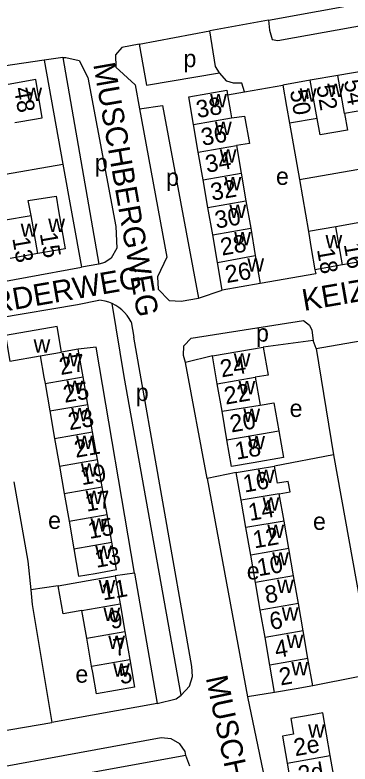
# Model space of a CAD drawing. Extents: x 162883 to 165538, y 383986 to 385172.
# Drawn here: x 164211.1 to 164288.3, y 384571.7 to 384744.4 of the extents above; entities that cross this region are included whole.
import ezdxf

# ---------------------------------------------------------------- set-up
doc = ezdxf.new("R2010")
doc.units = 0
for name, color, linetype in [('BLT_Basislijn', 7, 'Continuous'), ('BLT_Bebouwing', 7, 'Continuous'), ('BLT_Centroide', 7, 'Continuous'), ('BLT_Huisnummer', 7, 'Continuous'), ('BLT_Huisnummer_ tussenligend', 7, 'Continuous'), ('BLT_Onderverdeling_panden', 7, 'Continuous'), ('BLT_Straatnaam', 7, 'Continuous')]:
    doc.layers.add(name, color=color, linetype=linetype)

msp = doc.modelspace()

# ---------------------------------------------------------------- linework, layer by layer
at = {"layer": 'BLT_Basislijn'}
for p, q in [((164269.53, 384743.17), (164347.88, 384757.52)), ((164269.53, 384743.17), (164255.95, 384740.69)), ((164239.7, 384737.66), (164255.95, 384740.69)), ((164222.1, 384734.54), (164217.84, 384733.93)), ((164217.84, 384733.93), (164222.14, 384709.97)), ((164222.1, 384734.54), (164230.42, 384686.92)), ((164260.07, 384725.97), (164263.99, 384726.67)), ((164263.99, 384726.67), (164272.76, 384728.22)), ((164274.3, 384719.42), (164276.6, 384706.41)), ((164168.6, 384700.69), (164222.14, 384709.97)), ((164222.14, 384709.97), (164226.46, 384686.21)), ((164276.6, 384706.41), (164278.71, 384694.44)), ((164230.42, 384686.92), (164226.46, 384686.21)), ((164253.38, 384679.08), (164258.85, 384680.93)), ((164225.48, 384677.63), (164230.4, 384678.65)), ((164207.26, 384674.54), (164225.48, 384677.63)), ((164237.86, 384673.64), (164238.49, 384670.06)), ((164280.45, 384667.49), (164307.71, 384672.24)), ((164279.77, 384669.33), (164268.29, 384667.79)), ((164280.45, 384667.49), (164279.77, 384669.33)), ((164280.45, 384667.49), (164284.49, 384642.92)), ((164256.56, 384665.75), (164250.41, 384664.28)), ((164255.34, 384637.53), (164250.41, 384664.28)), ((164284.49, 384642.92), (164270.86, 384640.38)), ((164284.49, 384642.92), (164293.58, 384592.09)), ((164262.08, 384638.85), (164255.34, 384637.53)), ((164255.34, 384637.53), (164264.67, 384587.17)), ((164238.61, 384615.65), (164234.19, 384615.04)), ((164238.61, 384615.65), (164243.86, 384585.6)), ((164221.03, 384612.73), (164214.72, 384611.85)), ((164290.18, 384591.77), (164279.69, 384589.68)), ((164270.91, 384588.15), (164264.67, 384587.17)), ((164243.86, 384585.6), (164219.61, 384581.22)), ((164251.35, 384571.17), (164250.47, 384573.67))]:
    msp.add_line(p, q, dxfattribs=at)
for points in [[(164269.53, 384743.17), (164269.71, 384740.85), (164270.34, 384738.74), (164271.65, 384738.47), (164348.49, 384752.42), (164347.88, 384757.52)], [(164258.17, 384731), (164257.32, 384732.52), (164255.95, 384740.69)], [(164239.7, 384737.66), (164235.73, 384736.91), (164234.23, 384735.22), (164234.36, 384732.34), (164238.75, 384728.3), (164239.75, 384722.77)], [(164239.7, 384737.66), (164241.36, 384728.2), (164258.17, 384731)], [(164217.84, 384733.93), (164208.48, 384732.56), (164171.26, 384725.9), (164163.09, 384724.16), (164161.59, 384723.02), (164160.96, 384722.06), (164160.7, 384719.23), (164161.02, 384716.34), (164167.7, 384681.66), (164168.5, 384679.45), (164169.93, 384677.77), (164172.47, 384676.74), (164176.29, 384676.98), (164226.46, 384686.21)], [(164222.1, 384734.54), (164222.84, 384734.6), (164225.86, 384733.87), (164227.92, 384729.96), (164234.34, 384695.57), (164234.58, 384690.61), (164233.24, 384688.27), (164231.79, 384687.29), (164230.42, 384686.92)], [(164263.99, 384726.67), (164263.37, 384728.62), (164261.46, 384728.67), (164259.9, 384729.09), (164258.17, 384731)], [(164239.75, 384722.77), (164245.09, 384723.48), (164253.38, 384679.08)], [(164239.75, 384722.77), (164246.07, 384688.5), (164243.9, 384683.98), (164244.11, 384681.13), (164246.59, 384678.53), (164249.39, 384678.37), (164253.38, 384679.08)], [(164276.6, 384706.41), (164333.43, 384716.36), (164335.7, 384704.35)], [(164280.2, 384685.63), (164280.37, 384684.68), (164267.57, 384682.44)], [(164233.47, 384677.81), (164232.74, 384678.12), (164231.91, 384678.38), (164231.06, 384678.57), (164230.4, 384678.65)], [(164249.37, 384587.52), (164236.28, 384660.98), (164233.47, 384677.81)], [(164237.86, 384673.64), (164237.42, 384674.39), (164236.91, 384675.1), (164236.34, 384675.75), (164235.71, 384676.36), (164235.04, 384676.9), (164234.31, 384677.37), (164233.47, 384677.81)], [(164250.41, 384664.28), (164249.95, 384665.84), (164250, 384668.1), (164251.7, 384669.85), (164277.56, 384673.96), (164278.9, 384672.84), (164279.49, 384671.72), (164279.77, 384669.33)], [(164249.37, 384587.52), (164251.28, 384589.64), (164251.96, 384591.87), (164251.86, 384594.15), (164238.49, 384670.06)], [(164238.61, 384615.65), (164229.77, 384667.77), (164225.68, 384667.29)], [(164210.85, 384636.76), (164214.03, 384618.46), (164214.72, 384611.85)], [(164187.23, 384632.57), (164197, 384577.38), (164219.61, 384581.22)], [(164214.72, 384611.85), (164215.08, 384608.41), (164219.61, 384581.22)], [(164243.86, 384585.6), (164248.2, 384586.72), (164249.37, 384587.52)], [(164264.67, 384587.17), (164270.15, 384560.59), (164276.83, 384536.76), (164279.31, 384533.9), (164282.01, 384533.02), (164284.05, 384532.85)], [(164250.47, 384573.67), (164250.27, 384574.53), (164249.08, 384576.32), (164247.1, 384577.51), (164244.79, 384577.71), (164126.03, 384555.88), (164121.95, 384556.13), (164120.84, 384556.55), (164118.27, 384559.19), (164117.27, 384561.39), (164113.93, 384561.01), (164112.88, 384567.21), (164114.89, 384567.71), (164116.32, 384568.96), (164116.32, 384571.03), (164115.14, 384572.4), (164108.09, 384571.67)], [(164250.47, 384573.67), (164216.18, 384567.37)]]:
    msp.add_lwpolyline(points, dxfattribs=at)
at = {"layer": 'BLT_Bebouwing'}
for p, q in [((164285.44, 384730.43), (164279.1, 384729.33)), ((164291.77, 384731.53), (164285.44, 384730.43)), ((164279.1, 384729.33), (164272.76, 384728.22)), ((164293.3, 384722.77), (164287.03, 384721.68)), ((164280.73, 384720.53), (164274.3, 384719.42)), ((164253.32, 384712.75), (164252.21, 384719.11)), ((164262.1, 384714.27), (164263.21, 384707.91)), ((164254.43, 384706.38), (164253.32, 384712.75)), ((164263.21, 384707.91), (164264.31, 384701.55)), ((164255.53, 384700.02), (164254.43, 384706.38)), ((164264.31, 384701.55), (164265.42, 384695.18)), ((164256.64, 384693.66), (164255.53, 384700.02)), ((164208.47, 384697.06), (164214.82, 384698.15)), ((164285.01, 384695.54), (164278.71, 384694.44)), ((164291.35, 384696.64), (164285.01, 384695.54)), ((164257.75, 384687.29), (164256.64, 384693.66)), ((164216.33, 384689.36), (164209.99, 384688.26)), ((164258.85, 384680.93), (164257.75, 384687.29)), ((164292.88, 384687.83), (164286.54, 384686.73)), ((164286.54, 384686.73), (164280.2, 384685.63)), ((164226.78, 384660.94), (164225.68, 384667.29)), ((164256.56, 384665.75), (164268.29, 384667.79)), ((164257.69, 384659.31), (164256.56, 384665.75)), ((164218.03, 384659.42), (164219.14, 384653.07)), ((164227.89, 384654.59), (164226.78, 384660.94)), ((164258.79, 384653), (164257.69, 384659.31)), ((164266.42, 384660.83), (164267.54, 384654.39)), ((164228.99, 384648.24), (164227.89, 384654.59)), ((164219.14, 384653.07), (164220.24, 384646.71)), ((164259.93, 384646.44), (164258.79, 384653)), ((164230.1, 384641.89), (164228.99, 384648.24)), ((164220.24, 384646.71), (164221.35, 384640.36)), ((164221.35, 384640.36), (164222.45, 384634.01)), ((164231.21, 384635.54), (164230.1, 384641.89)), ((164263.18, 384632.51), (164262.08, 384638.85)), ((164232.31, 384629.18), (164231.21, 384635.54)), ((164222.45, 384634.01), (164223.56, 384627.66)), ((164273.07, 384627.7), (164271.98, 384633.95)), ((164264.29, 384626.18), (164263.18, 384632.51)), ((164233.42, 384622.83), (164232.31, 384629.18)), ((164223.56, 384627.66), (164224.67, 384621.31)), ((164274.17, 384621.37), (164273.07, 384627.7)), ((164265.39, 384619.84), (164264.29, 384626.18)), ((164275.28, 384615.03), (164274.17, 384621.37)), ((164266.5, 384613.5), (164265.39, 384619.84)), ((164234.19, 384615.04), (164235.31, 384608.62)), ((164276.38, 384608.69), (164275.28, 384615.03)), ((164267.6, 384607.16), (164266.5, 384613.5)), ((164235.31, 384608.62), (164236.43, 384602.21)), ((164277.49, 384602.35), (164276.38, 384608.69)), ((164227.64, 384600.67), (164226.52, 384607.09)), ((164268.71, 384600.82), (164267.6, 384607.16)), ((164278.59, 384596.02), (164277.49, 384602.35)), ((164228.75, 384594.26), (164227.64, 384600.67)), ((164236.43, 384602.21), (164237.54, 384595.79)), ((164269.81, 384594.49), (164268.71, 384600.82)), ((164279.69, 384589.68), (164278.59, 384596.02)), ((164270.91, 384588.15), (164269.81, 384594.49)), ((164285.43, 384563.8), (164283.72, 384573.6))]:
    msp.add_line(p, q, dxfattribs=at)
for points in [[(164211.05, 384719.58), (164212.47, 384719.82), (164217.39, 384720.67), (164215.88, 384729.46), (164209.54, 384728.36)], [(164252.21, 384719.11), (164251.11, 384725.47), (164259.89, 384727), (164260.07, 384725.97)], [(164272.76, 384728.22), (164273.62, 384723.29), (164274.3, 384719.42)], [(164260.07, 384725.97), (164260.74, 384722.07), (164260.99, 384720.64)], [(164287.03, 384721.68), (164287.7, 384717.81), (164281.39, 384716.71), (164280.73, 384720.53)], [(164260.99, 384720.64), (164263.99, 384721.07), (164265.09, 384714.74), (164262.1, 384714.27)], [(164214.82, 384698.15), (164214.16, 384701.58), (164220.57, 384702.63), (164221.16, 384699.25), (164222.68, 384690.45), (164216.33, 384689.36)], [(164265.42, 384695.18), (164266.45, 384688.89)], [(164278.71, 384694.44), (164279.35, 384690.56), (164280.2, 384685.63)], [(164266.45, 384688.89), (164267.57, 384682.44)], [(164267.57, 384682.44), (164258.85, 384680.93)], [(164221.85, 384666.62), (164220.82, 384672.54), (164208.9, 384670.46), (164209.93, 384664.52)], [(164225.68, 384667.29), (164221.85, 384666.62)], [(164268.29, 384667.79), (164269.41, 384661.35), (164266.42, 384660.83)], [(164209.93, 384664.52), (164216.93, 384665.77)], [(164216.93, 384665.77), (164217.78, 384660.86), (164218.03, 384659.42)], [(164267.54, 384654.39), (164270.75, 384654.95), (164271.87, 384648.52)], [(164271.87, 384648.52), (164272.95, 384642.32), (164265.93, 384641.1), (164261.01, 384640.24), (164259.93, 384646.44)], [(164262.08, 384638.85), (164267.12, 384639.73), (164270.86, 384640.38)], [(164271.98, 384633.95), (164274.46, 384634.43), (164274.04, 384636.84), (164271.55, 384636.41), (164270.86, 384640.38)], [(164224.67, 384621.31), (164225.77, 384614.95), (164229.6, 384615.62), (164234.52, 384616.48), (164233.42, 384622.83)], [(164221.03, 384612.73), (164229.27, 384614.19), (164234.19, 384615.04)], [(164226.52, 384607.09), (164222.17, 384606.29), (164221.03, 384612.73)], [(164237.54, 384595.79), (164238.66, 384589.39), (164229.87, 384587.85), (164229.01, 384592.79), (164228.75, 384594.26)], [(164279.69, 384589.68), (164275.84, 384589.01), (164270.91, 384588.15)], [(164283.72, 384573.6), (164282, 384583.45), (164279.57, 384583.03), (164274.66, 384582.17), (164275.29, 384578.57), (164272.71, 384578.12), (164273.8, 384571.86)], [(164273.8, 384571.86), (164274.88, 384565.66), (164274.19, 384565.54), (164274.75, 384561.93)]]:
    msp.add_lwpolyline(points, dxfattribs=at)
at = {"layer": 'BLT_Onderverdeling_panden'}
for p, q in [((164287.03, 384721.68), (164285.44, 384730.43)), ((164280.73, 384720.53), (164279.1, 384729.33)), ((164252.21, 384719.11), (164260.99, 384720.64)), ((164253.32, 384712.75), (164262.1, 384714.27)), ((164254.43, 384706.38), (164263.21, 384707.91)), ((164255.53, 384700.02), (164264.31, 384701.55)), ((164216.33, 384689.36), (164214.82, 384698.15)), ((164286.54, 384686.73), (164285.01, 384695.54)), ((164256.64, 384693.66), (164265.42, 384695.18)), ((164257.75, 384687.29), (164266.45, 384688.89)), ((164216.93, 384665.77), (164221.85, 384666.62)), ((164218.03, 384659.42), (164226.78, 384660.94)), ((164257.69, 384659.31), (164266.42, 384660.83)), ((164219.14, 384653.07), (164227.89, 384654.59)), ((164258.79, 384653), (164267.54, 384654.39)), ((164220.24, 384646.71), (164228.99, 384648.24)), ((164259.93, 384646.44), (164271.87, 384648.52)), ((164221.35, 384640.36), (164230.1, 384641.89)), ((164222.45, 384634.01), (164231.21, 384635.54)), ((164271.98, 384633.95), (164263.18, 384632.51)), ((164223.56, 384627.66), (164232.31, 384629.18)), ((164273.07, 384627.7), (164264.29, 384626.18)), ((164224.67, 384621.31), (164233.42, 384622.83)), ((164274.17, 384621.37), (164265.39, 384619.84)), ((164275.28, 384615.03), (164266.5, 384613.5)), ((164226.52, 384607.09), (164235.31, 384608.62)), ((164276.38, 384608.69), (164267.6, 384607.16)), ((164277.49, 384602.35), (164268.71, 384600.82)), ((164227.64, 384600.67), (164236.43, 384602.21)), ((164228.75, 384594.26), (164237.54, 384595.79)), ((164278.59, 384596.02), (164269.81, 384594.49)), ((164273.8, 384571.86), (164283.72, 384573.6))]:
    msp.add_line(p, q, dxfattribs=at)

# ---------------------------------------------------------------- texts
at = {"layer": 'BLT_Centroide'}
for s, p in [('p', (164249.91, 384732.34)), ('w', (164283.03, 384725.48)), ('w', (164213.47, 384724.52)), ('w', (164276.69, 384724.39)), ('w', (164256.05, 384723.06)), ('w', (164257.16, 384716.69)), ('w', (164258.26, 384710.34)), ('p', (164229.5, 384708.33)), ('p', (164245.88, 384704.96)), ('e', (164271.22, 384705.19)), ('w', (164259.37, 384703.97)), ('w', (164260.48, 384697.59)), ('w', (164218.75, 384694.31)), ('w', (164212.41, 384693.22)), ('w', (164261.59, 384691.25)), ('w', (164282.62, 384690.59)), ('w', (164264.62, 384685.22)), ('p', (164266.61, 384669.06)), ('w', (164215.38, 384666.53)), ('w', (164221.85, 384663.34)), ('w', (164261.48, 384663.31)), ('w', (164222.96, 384657)), ('w', (164262.59, 384656.94)), ('p', (164238.92, 384655.37)), ('e', (164274.36, 384651.69)), ('w', (164224.07, 384650.66)), ('w', (164263.7, 384650.56)), ('w', (164225.16, 384644.31)), ('w', (164264.81, 384644.19)), ('w', (164226.27, 384637.94)), ('w', (164267.02, 384636.44)), ('w', (164227.38, 384631.59)), ('w', (164268.13, 384630.09)), ('e', (164218.73, 384625.88)), ('w', (164228.49, 384625.25)), ('e', (164279.74, 384625.65)), ('w', (164269.23, 384623.78)), ('w', (164229.59, 384618.91)), ('w', (164270.34, 384617.44)), ('e', (164264.49, 384614.21)), ('w', (164230.36, 384611.06)), ('w', (164271.45, 384611.09)), ('w', (164231.47, 384604.66)), ('w', (164272.54, 384604.75)), ('w', (164232.59, 384598.22)), ('w', (164273.65, 384598.41)), ('w', (164233.7, 384591.81)), ('w', (164274.76, 384592.09)), ('e', (164225.02, 384590.42)), ('w', (164278.6, 384577.78))]:
    msp.add_text(s, height=4, dxfattribs=at).set_placement(p)
at = {"layer": 'BLT_Huisnummer'}
for s, rotation, p in [('54', 279.8576, (164286.84, 384729.2)), ('48', 279.7868, (164210.84, 384727.47)), ('50', 279.8576, (164274.4, 384726.88)), ('38', 9.8609, (164253.17, 384720.59)), ('34', 9.8609, (164255.3, 384707.98)), ('30', 9.8609, (164257.49, 384695.1)), ('15', 279.7811, (164216.81, 384693.96)), ('18', 279.8639, (164280.65, 384690.29)), ('26', 9.8609, (164259.87, 384682.54)), ('27', 9.9723, (164221.64, 384661.34)), ('24', 9.8805, (164258.71, 384660.8)), ('21', 9.9723, (164225.11, 384642.26)), ('18', 9.8805, (164262.13, 384641.82)), ('16', 9.8805, (164263.99, 384634.25)), ('17', 9.9723, (164227.62, 384629.84)), ('13', 9.9723, (164229.83, 384616.89)), ('10', 9.8805, (164267.22, 384614.94)), ('11', 9.9723, (164231.4, 384609.38)), ('6', 9.8805, (164270.09, 384602.56)), ('5', 9.9723, (164235.44, 384590.05)), ('2', 9.8805, (164272.28, 384589.76)), ('2e', 9.8825, (164275.65, 384573.46))]:
    msp.add_text(s, height=4, rotation=rotation, dxfattribs=at).set_placement(p)
at = {"layer": 'BLT_Huisnummer_ tussenligend'}
for s, rotation, p in [('52', 279.8576, (164280.5, 384727.97)), ('36', 9.8609, (164254.31, 384714.19)), ('32', 9.8609, (164256.51, 384701.53)), ('13', 279.7811, (164210.48, 384692.88)), ('28', 9.8609, (164258.77, 384688.87)), ('16', 279.8639, (164286.83, 384691.47)), ('25', 9.9723, (164222.56, 384654.94)), ('22', 9.8805, (164259.64, 384654.52)), ('23', 9.9723, (164223.67, 384648.62)), ('20', 9.8805, (164260.95, 384648.09)), ('19', 9.9723, (164226.52, 384635.94)), ('14', 9.8805, (164265.2, 384627.7)), ('15', 9.9723, (164228.27, 384623.55)), ('12', 9.8805, (164266.24, 384621.37)), ('8', 9.8805, (164268.99, 384608.66)), ('9', 9.9723, (164233.24, 384602.77)), ('7', 9.9723, (164234.1, 384596.48)), ('4', 9.8805, (164271.27, 384596.08)), ('2d', 9.8853, (164276.66, 384567.19))]:
    msp.add_text(s, height=4, rotation=rotation, dxfattribs=at).set_placement(p)
at = {"layer": 'BLT_Straatnaam'}
for s, height, rotation, p in [('MUSCHBERGWEG', 4.9999, 279.9221, (164229.11, 384733)), ('KEIZERSMANTELSTRAAT', 5, 9.8188, (164277.68, 384676.11)), ('WILGEBOORDERWEG', 4.9999, 9.8944, (164170.34, 384669.3)), ('MUSCHBERGWEG', 5, 281.9221, (164255.02, 384591.56))]:
    msp.add_text(s, height=height, rotation=rotation, dxfattribs=at).set_placement(p)

doc.saveas('drawing.dxf')
